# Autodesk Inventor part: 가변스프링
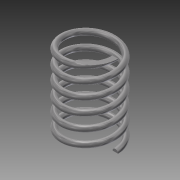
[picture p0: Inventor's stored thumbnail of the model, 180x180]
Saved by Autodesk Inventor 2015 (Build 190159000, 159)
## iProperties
Created: 2015-10
Part Number: 가변스프링
Material: Steel, Mild
Document SubType Name: Modeling
Designer: youjin05
Mass: 128.878 g
Surface Area: 133.051 cm^2
Volume: 16.4176 cm^3
Density: 7.85 g/cm^3
Appearance: Semi-Polished
Author: youjin05
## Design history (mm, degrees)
sketch "Sketch1"
  geometry: L1 (0, 0)-(-22.5, 0); L2 (-22.5, 0)-(-22.5, 73.25); L3 (-22.5, 73.25)-(0, 73.25); L4 (0, 73.25)-(0, 0); C1 r 2.5 at (-22.5, 0)
  constraints: 8 end point, 2 parallel, 1 centre point, 1 coincident, 1 horizontal, 1 perpendicular
  dimensions: "d0" = 73.25 distance between parallel lines of L1 L3 (derived); "d1" = 45 diameter of L2 L4; "d2" = 5 diameter of C1
coil "Coil1" pitch "d3" = 10; turns "d5" = 6; dims "d4" = 73.25 (= d0), "d6" = 0, angle "d7" = 90 deg, angle "d8" = 90 deg, "d9" = 0, "d10" = 0
sketch "Sketch2"
  geometry: L1 (25, 0)-(20, 0) reference; 1 further point
  constraints: 1 horizontal alignment
extrude "Extrusion1" cut sketch "Sketch2" stored distance "d11" = 10; taper "d12" = 0 deg
workplane "Work Plane1"
sketch "Sketch3"
  geometry: L1 (20, 0)-(25, 0) reference; 1 further point
  constraints: 1 horizontal alignment
extrude "Extrusion2" cut sketch "Sketch3" stored distance "d13" = 10; taper "d14" = 0 deg
body "Solid1"
node "Project Cut Edges1"
node "Project Cut Edges2"
